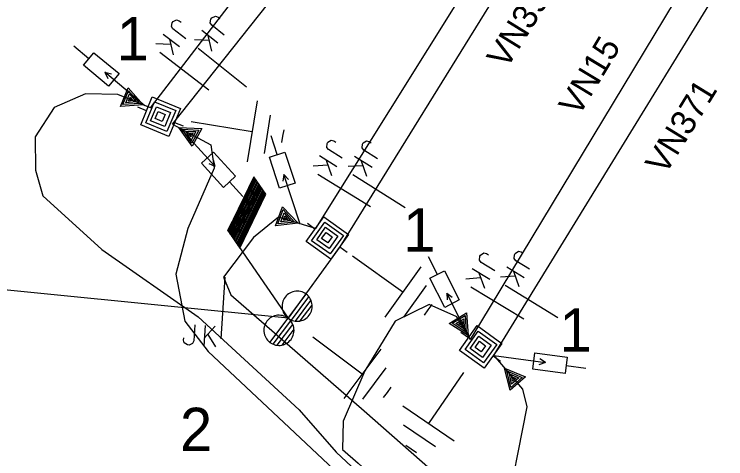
# Model space of a CAD drawing. Extents: x -540340 to -537226, y -1183949 to -1180375.
# Drawn here: x -537543.05 to -537514.32, y -1180671.08 to -1180653.13 of the extents above; entities that cross this region are included whole.
import ezdxf

# ---------------------------------------------------------------- set-up
doc = ezdxf.new("R2010")
doc.units = 0
for name, color, linetype in [('Vrstva 1', 7, 'Continuous'), ('Vrstva 11', 7, 'Continuous'), ('Vrstva 13', 7, 'Continuous'), ('Vrstva 14', 7, 'Continuous'), ('Vrstva 15', 7, 'Continuous'), ('Vrstva 16', 7, 'Continuous'), ('Vrstva 18', 7, 'Continuous'), ('Vrstva 19', 7, 'Continuous'), ('Vrstva 3', 7, 'Continuous'), ('Vrstva 5', 7, 'Continuous')]:
    doc.layers.add(name, color=color, linetype=linetype)

msp = doc.modelspace()

# ---------------------------------------------------------------- linework, layer by layer
at = {"layer": 'Vrstva 1'}
for points in [[(-537537.553, -1180656.912), (-537521.871, -1180636.493)], [(-537536.659, -1180657.565), (-537520.59, -1180637.312)], [(-537517.243, -1180639.978), (-537530.88, -1180661.777)], [(-537516.363, -1180640.64), (-537529.897, -1180662.526), (-537531.994, -1180665.405)], [(-537524.622, -1180666.267), (-537524.208, -1180665.581), (-537511.413, -1180644.384)], [(-537523.685, -1180666.914), (-537523.331, -1180666.336), (-537510.283, -1180645.074)], [(-537531.994, -1180665.406), (-537572.36, -1180661.377), (-537627.262, -1180751.899)]]:
    msp.add_lwpolyline(points, dxfattribs=at)
at = {"layer": 'Vrstva 11'}
for p, q in [((-537534.393, -1180661.91), (-537533.341, -1180659.735)), ((-537534.36, -1180661.957), (-537533.309, -1180659.783)), ((-537534.328, -1180662.005), (-537533.276, -1180659.83)), ((-537534.295, -1180662.052), (-537533.244, -1180659.878)), ((-537534.263, -1180662.1), (-537533.212, -1180659.926)), ((-537534.23, -1180662.147), (-537533.179, -1180659.974)), ((-537534.197, -1180662.195), (-537533.147, -1180660.021)), ((-537534.165, -1180662.242), (-537533.114, -1180660.069)), ((-537534.132, -1180662.29), (-537533.082, -1180660.117)), ((-537534.1, -1180662.337), (-537533.049, -1180660.165)), ((-537534.067, -1180662.385), (-537533.017, -1180660.212)), ((-537534.035, -1180662.432), (-537532.984, -1180660.26)), ((-537534.002, -1180662.48), (-537532.952, -1180660.308)), ((-537533.969, -1180662.527), (-537532.92, -1180660.356)), ((-537534.425, -1180661.862), (-537534.246, -1180661.492))]:
    msp.add_line(p, q, dxfattribs=at)
msp.add_lwpolyline([(-537533.371, -1180659.691), (-537534.426, -1180661.862), (-537533.939, -1180662.572), (-537532.89, -1180660.4)], close=True, dxfattribs=at)
msp.add_lwpolyline([(-537534.426, -1180661.862), (-537531.994, -1180665.405)], dxfattribs=at)
at = {"layer": 'Vrstva 13'}
for points in [[(-537537.945, -1180657.595), (-537537.476, -1180656.46)], [(-537537.735, -1180657.516), (-537537.384, -1180656.664)], [(-537537.476, -1180656.46), (-537536.34, -1180656.929)], [(-537537.384, -1180656.664), (-537536.532, -1180657.016)], [(-537537.71, -1180657.028), (-537538.056, -1180656.885)], [(-537537.544, -1180657.429), (-537537.309, -1180656.861)], [(-537537.309, -1180656.861), (-537536.741, -1180657.095)], [(-537536.532, -1180657.016), (-537536.883, -1180657.867)], [(-537536.34, -1180656.929), (-537536.809, -1180658.064)], [(-537537.361, -1180657.338), (-537537.244, -1180657.054)], [(-537537.244, -1180657.054), (-537536.96, -1180657.171)], [(-537536.96, -1180657.171), (-537537.077, -1180657.455)], [(-537536.741, -1180657.095), (-537536.976, -1180657.663)], [(-537536.883, -1180657.867), (-537537.735, -1180657.516)], [(-537536.976, -1180657.663), (-537537.544, -1180657.429)], [(-537537.077, -1180657.455), (-537537.361, -1180657.338)], [(-537536.575, -1180657.496), (-537536.229, -1180657.639)], [(-537536.809, -1180658.064), (-537537.945, -1180657.595)], [(-537531.264, -1180662.301), (-537530.548, -1180661.304)], [(-537530.548, -1180661.304), (-537529.55, -1180662.02)], [(-537530.906, -1180661.803), (-537531.21, -1180661.584)], [(-537531.042, -1180662.272), (-537530.504, -1180661.524)], [(-537530.504, -1180661.524), (-537529.756, -1180662.061)], [(-537530.835, -1180662.231), (-537530.477, -1180661.732)], [(-537530.477, -1180661.732), (-537529.978, -1180662.091)], [(-537530.637, -1180662.185), (-537530.458, -1180661.935)], [(-537530.387, -1180662.364), (-537530.637, -1180662.185)], [(-537530.458, -1180661.935), (-537530.208, -1180662.114)], [(-537530.208, -1180662.114), (-537530.387, -1180662.364)], [(-537529.978, -1180662.091), (-537530.336, -1180662.589)], [(-537529.756, -1180662.061), (-537530.293, -1180662.809)], [(-537529.55, -1180662.02), (-537530.266, -1180663.018)], [(-537530.266, -1180663.018), (-537531.264, -1180662.301)], [(-537530.293, -1180662.809), (-537531.042, -1180662.272)], [(-537530.336, -1180662.589), (-537530.835, -1180662.231)], [(-537529.908, -1180662.519), (-537529.604, -1180662.737)], [(-537532.727, -1180666.378), (-537531.261, -1180664.432)], [(-537531.261, -1180664.432), (-537531.314, -1180664.396), (-537531.37, -1180664.366), (-537531.429, -1180664.343), (-537531.49, -1180664.325), (-537531.553, -1180664.314), (-537531.617, -1180664.31), (-537531.68, -1180664.312), (-537531.743, -1180664.321), (-537531.805, -1180664.336), (-537531.865, -1180664.358), (-537531.923, -1180664.386), (-537531.977, -1180664.42), (-537532.027, -1180664.459), (-537532.073, -1180664.503), (-537532.114, -1180664.552), (-537532.15, -1180664.605), (-537532.18, -1180664.661), (-537532.203, -1180664.72), (-537532.221, -1180664.782), (-537532.232, -1180664.845), (-537532.236, -1180664.908), (-537532.234, -1180664.972), (-537532.225, -1180665.035), (-537532.21, -1180665.097), (-537532.188, -1180665.157), (-537532.16, -1180665.214), (-537532.126, -1180665.268), (-537532.087, -1180665.319), (-537532.043, -1180665.364), (-537531.994, -1180665.405), (-537531.941, -1180665.441), (-537531.885, -1180665.471), (-537531.826, -1180665.495), (-537531.764, -1180665.512), (-537531.701, -1180665.524), (-537531.638, -1180665.528), (-537531.574, -1180665.526), (-537531.511, -1180665.517), (-537531.449, -1180665.501), (-537531.389, -1180665.479), (-537531.332, -1180665.451), (-537531.278, -1180665.418), (-537531.227, -1180665.379), (-537531.182, -1180665.334), (-537531.141, -1180665.285), (-537531.105, -1180665.232), (-537531.075, -1180665.176), (-537531.051, -1180665.117), (-537531.034, -1180665.056), (-537531.022, -1180664.993), (-537531.018, -1180664.929), (-537531.02, -1180664.865), (-537531.029, -1180664.803), (-537531.045, -1180664.741), (-537531.066, -1180664.681), (-537531.094, -1180664.623), (-537531.128, -1180664.569), (-537531.167, -1180664.519), (-537531.212, -1180664.473), (-537531.26, -1180664.432)], [(-537531.86, -1180665.482), (-537531.15, -1180664.54)], [(-537531.697, -1180665.521), (-537531.067, -1180664.686)], [(-537531.499, -1180665.514), (-537531.02, -1180664.878)], [(-537531.994, -1180665.405), (-537532.047, -1180665.37), (-537532.103, -1180665.34), (-537532.162, -1180665.316), (-537532.224, -1180665.298), (-537532.287, -1180665.287), (-537532.35, -1180665.283), (-537532.414, -1180665.285), (-537532.477, -1180665.294), (-537532.539, -1180665.309), (-537532.599, -1180665.331), (-537532.656, -1180665.359), (-537532.71, -1180665.393), (-537532.761, -1180665.432), (-537532.806, -1180665.476), (-537532.847, -1180665.525), (-537532.883, -1180665.578), (-537532.913, -1180665.634), (-537532.937, -1180665.694), (-537532.954, -1180665.755), (-537532.966, -1180665.818), (-537532.97, -1180665.881), (-537532.968, -1180665.945), (-537532.959, -1180666.008), (-537532.943, -1180666.07), (-537532.921, -1180666.13), (-537532.893, -1180666.187), (-537532.86, -1180666.242), (-537532.821, -1180666.292), (-537532.776, -1180666.338), (-537532.727, -1180666.379), (-537532.674, -1180666.414), (-537532.618, -1180666.444), (-537532.559, -1180666.468), (-537532.498, -1180666.486), (-537532.435, -1180666.497), (-537532.371, -1180666.501), (-537532.307, -1180666.499), (-537532.245, -1180666.49), (-537532.183, -1180666.475), (-537532.123, -1180666.453), (-537532.065, -1180666.425), (-537532.011, -1180666.391), (-537531.961, -1180666.352), (-537531.915, -1180666.308), (-537531.874, -1180666.259), (-537531.838, -1180666.206), (-537531.808, -1180666.15), (-537531.785, -1180666.09), (-537531.767, -1180666.029), (-537531.756, -1180665.966), (-537531.752, -1180665.903), (-537531.754, -1180665.839), (-537531.763, -1180665.776), (-537531.778, -1180665.714), (-537531.8, -1180665.654), (-537531.828, -1180665.597), (-537531.862, -1180665.542), (-537531.901, -1180665.492), (-537531.945, -1180665.446), (-537531.994, -1180665.405)], [(-537532.593, -1180666.455), (-537531.883, -1180665.513)], [(-537532.43, -1180666.494), (-537531.801, -1180665.659)], [(-537532.232, -1180666.487), (-537531.753, -1180665.851)], [(-537525.07, -1180666.701), (-537524.353, -1180665.703)], [(-537524.847, -1180666.672), (-537524.31, -1180665.923)], [(-537524.353, -1180665.703), (-537523.355, -1180666.42)], [(-537524.31, -1180665.923), (-537523.562, -1180666.461)], [(-537524.711, -1180666.202), (-537525.015, -1180665.984)], [(-537524.641, -1180666.631), (-537524.283, -1180666.132)], [(-537524.283, -1180666.132), (-537523.784, -1180666.49)], [(-537524.442, -1180666.584), (-537524.263, -1180666.335)], [(-537524.263, -1180666.335), (-537524.014, -1180666.514)], [(-537523.784, -1180666.49), (-537524.142, -1180666.989)], [(-537523.562, -1180666.461), (-537524.099, -1180667.209)], [(-537523.355, -1180666.42), (-537524.072, -1180667.418)], [(-537524.072, -1180667.418), (-537525.07, -1180666.701)], [(-537524.099, -1180667.209), (-537524.847, -1180666.672)], [(-537524.142, -1180666.989), (-537524.641, -1180666.631)], [(-537524.193, -1180666.764), (-537524.442, -1180666.584)], [(-537524.014, -1180666.514), (-537524.193, -1180666.764)], [(-537523.713, -1180666.919), (-537523.41, -1180667.137)]]:
    msp.add_lwpolyline(points, dxfattribs=at)
at = {"layer": 'Vrstva 15'}
for points in [[(-537533.245, -1180656.623), (-537533.646, -1180659.091)], [(-537532.71, -1180657.198), (-537532.963, -1180658.753)], [(-537535.913, -1180657.456), (-537533.445, -1180657.857)], [(-537532.169, -1180657.795), (-537532.212, -1180658.057)], [(-537532.212, -1180658.057), (-537532.253, -1180658.31)], [(-537529.392, -1180662.882), (-537527.36, -1180664.339)], [(-537526.632, -1180663.323), (-537528.088, -1180665.355)], [(-537526.409, -1180664.076), (-537527.326, -1180665.356)], [(-537526.189, -1180664.851), (-537526.344, -1180665.067)], [(-537526.344, -1180665.067), (-537526.493, -1180665.275)], [(-537530.995, -1180666.149), (-537528.996, -1180667.65)], [(-537528.246, -1180666.651), (-537529.747, -1180668.65)], [(-537528.039, -1180667.409), (-537528.985, -1180668.668)], [(-537524.913, -1180667.592), (-537526.318, -1180669.659)], [(-537527.837, -1180668.188), (-537527.997, -1180668.401)], [(-537527.997, -1180668.401), (-537528.15, -1180668.606)], [(-537525.285, -1180670.362), (-537527.352, -1180668.956)], [(-537526.032, -1180670.603), (-537527.335, -1180669.718)], [(-537527.021, -1180670.693), (-537527.233, -1180670.549)], [(-537526.801, -1180670.842), (-537527.021, -1180670.693)]]:
    msp.add_lwpolyline(points, dxfattribs=at)
at = {"layer": 'Vrstva 16'}
for points in [[(-537540.04, -1180654.93), (-537540.652, -1180654.419)], [(-537540.255, -1180655.187), (-537539.832, -1180654.681)], [(-537539.832, -1180654.681), (-537538.82, -1180655.527)], [(-537539.243, -1180656.033), (-537540.255, -1180655.187)], [(-537537.775, -1180656.824), (-537539.391, -1180655.473)], [(-537539.391, -1180655.473), (-537539.126, -1180655.54)], [(-537539.391, -1180655.473), (-537539.278, -1180655.721)], [(-537538.82, -1180655.527), (-537539.243, -1180656.033)], [(-537536.356, -1180657.726), (-537534.931, -1180659.277)], [(-537532.429, -1180658.798), (-537532.679, -1180658.042)], [(-537535.49, -1180659.148), (-537535.004, -1180658.702)], [(-537535.004, -1180658.702), (-537534.112, -1180659.673)], [(-537532.747, -1180658.903), (-537532.12, -1180658.697)], [(-537532.12, -1180658.697), (-537531.707, -1180659.949)], [(-537534.931, -1180659.277), (-537535.011, -1180659.016)], [(-537532.333, -1180660.156), (-537532.747, -1180658.903)], [(-537534.598, -1180660.12), (-537535.49, -1180659.148)], [(-537534.931, -1180659.277), (-537535.185, -1180659.175)], [(-537532.164, -1180659.602), (-537532.199, -1180659.873)], [(-537531.503, -1180661.603), (-537532.164, -1180659.602)], [(-537532.164, -1180659.602), (-537531.974, -1180659.799)], [(-537534.112, -1180659.673), (-537534.598, -1180660.12)], [(-537534.358, -1180659.9), (-537533.819, -1180660.487)], [(-537531.707, -1180659.949), (-537532.333, -1180660.156)], [(-537525.963, -1180663.638), (-537526.325, -1180662.928)], [(-537526.262, -1180663.79), (-537525.674, -1180663.491)], [(-537525.674, -1180663.491), (-537525.076, -1180664.666)], [(-537525.663, -1180664.965), (-537526.262, -1180663.79)], [(-537524.624, -1180666.27), (-537525.579, -1180664.393)], [(-537525.579, -1180664.393), (-537525.362, -1180664.558)], [(-537525.579, -1180664.393), (-537525.573, -1180664.665)], [(-537525.076, -1180664.666), (-537525.663, -1180664.965)], [(-537523.686, -1180666.911), (-537521.6, -1180667.198)], [(-537522.112, -1180667.455), (-537522.022, -1180666.802)], [(-537522.022, -1180666.802), (-537520.715, -1180666.981)], [(-537521.6, -1180667.198), (-537521.827, -1180667.047)], [(-537520.715, -1180666.981), (-537520.805, -1180667.635)], [(-537521.6, -1180667.198), (-537521.859, -1180667.281)], [(-537520.761, -1180667.313), (-537519.971, -1180667.422)], [(-537520.805, -1180667.635), (-537522.112, -1180667.455)]]:
    msp.add_lwpolyline(points, dxfattribs=at)
at = {"layer": 'Vrstva 18'}
for points in [[(-537535.107, -1180653.321), (-537535.071, -1180653.275)], [(-537535.071, -1180653.275), (-537534.925, -1180653.202)], [(-537534.925, -1180653.202), (-537534.822, -1180653.246)], [(-537534.822, -1180653.246), (-537534.745, -1180653.307)], [(-537536.704, -1180653.624), (-537536.675, -1180653.473)], [(-537536.675, -1180653.473), (-537536.639, -1180653.426)], [(-537536.639, -1180653.426), (-537536.494, -1180653.351)], [(-537536.494, -1180653.351), (-537536.39, -1180653.394)], [(-537536.39, -1180653.394), (-537536.312, -1180653.454)], [(-537535.139, -1180653.472), (-537535.107, -1180653.321)], [(-537535.078, -1180653.57), (-537535.139, -1180653.472)], [(-537536.642, -1180653.722), (-537536.704, -1180653.624)], [(-537536.127, -1180654.117), (-537536.642, -1180653.722)], [(-537534.825, -1180654.298), (-537535.474, -1180653.784)], [(-537534.569, -1180653.973), (-537535.078, -1180653.57)], [(-537536.379, -1180654.445), (-537537.035, -1180653.941)], [(-537536.785, -1180654.133), (-537536.63, -1180654.773)], [(-537535.227, -1180653.98), (-537535.082, -1180654.622)], [(-537536.736, -1180654.344), (-537537.328, -1180654.324)], [(-537535.181, -1180654.192), (-537535.773, -1180654.162)], [(-537535.194, -1180656.199), (-537537.177, -1180654.676)], [(-537533.666, -1180656.068), (-537535.627, -1180654.517)], [(-537530.432, -1180658.503), (-537530.418, -1180658.35)], [(-537530.418, -1180658.35), (-537530.387, -1180658.299)], [(-537530.387, -1180658.299), (-537530.251, -1180658.209)], [(-537530.251, -1180658.209), (-537530.144, -1180658.241)], [(-537530.144, -1180658.241), (-537530.06, -1180658.293)], [(-537529.005, -1180658.527), (-537528.991, -1180658.373)], [(-537528.991, -1180658.373), (-537528.959, -1180658.323)], [(-537528.959, -1180658.323), (-537528.822, -1180658.235)], [(-537528.822, -1180658.235), (-537528.715, -1180658.267)], [(-537528.715, -1180658.267), (-537528.632, -1180658.32)], [(-537530.36, -1180658.593), (-537530.432, -1180658.503)], [(-537529.807, -1180658.934), (-537530.36, -1180658.593)], [(-537528.934, -1180658.618), (-537529.005, -1180658.527)], [(-537528.384, -1180658.963), (-537528.934, -1180658.618)], [(-537530.024, -1180659.286), (-537530.728, -1180658.852)], [(-537530.46, -1180659.017), (-537530.24, -1180659.638)], [(-537528.603, -1180659.313), (-537529.304, -1180658.874)], [(-537530.389, -1180659.223), (-537530.981, -1180659.263)], [(-537528.968, -1180659.247), (-537529.56, -1180659.282)], [(-537529.037, -1180659.041), (-537528.823, -1180659.663)], [(-537528.665, -1180660.908), (-537530.794, -1180659.598)], [(-537527.257, -1180660.946), (-537529.376, -1180659.619)], [(-537524.222, -1180662.853), (-537524.086, -1180662.762)], [(-537524.086, -1180662.762), (-537523.979, -1180662.793)], [(-537522.82, -1180662.787), (-537522.684, -1180662.697)], [(-537522.684, -1180662.697), (-537522.576, -1180662.729)], [(-537522.576, -1180662.729), (-537522.493, -1180662.781)], [(-537524.264, -1180663.057), (-537524.252, -1180662.904)], [(-537524.252, -1180662.904), (-537524.222, -1180662.853)], [(-537523.979, -1180662.793), (-537523.894, -1180662.844)], [(-537522.864, -1180662.991), (-537522.851, -1180662.838)], [(-537522.793, -1180663.081), (-537522.864, -1180662.991)], [(-537522.851, -1180662.838), (-537522.82, -1180662.787)], [(-537524.192, -1180663.147), (-537524.264, -1180663.057)], [(-537523.636, -1180663.483), (-537524.192, -1180663.147)], [(-537522.239, -1180663.421), (-537522.793, -1180663.081)], [(-537523.85, -1180663.837), (-537524.558, -1180663.409)], [(-537524.288, -1180663.572), (-537524.063, -1180664.19)], [(-537522.455, -1180663.774), (-537523.16, -1180663.341)], [(-537522.891, -1180663.506), (-537522.671, -1180664.126)], [(-537534.541, -1180663.744), (-537534.71, -1180666.238)], [(-537524.216, -1180663.776), (-537524.807, -1180663.822)], [(-537522.821, -1180663.711), (-537523.412, -1180663.752)], [(-537522.476, -1180665.447), (-537524.617, -1180664.155)], [(-537521.094, -1180665.394), (-537523.225, -1180664.087)], [(-537535.757, -1180665.674), (-537535.801, -1180666.322)], [(-537535.345, -1180665.702), (-537535.401, -1180666.527)], [(-537535.379, -1180666.213), (-537534.933, -1180665.73)], [(-537536.214, -1180666.294), (-537536.207, -1180666.196)], [(-537535.231, -1180666.055), (-537534.92, -1180666.559)], [(-537536.192, -1180666.404), (-537536.214, -1180666.294)], [(-537536.049, -1180666.483), (-537536.192, -1180666.404)], [(-537535.99, -1180666.487), (-537536.049, -1180666.483)], [(-537535.848, -1180666.427), (-537535.99, -1180666.487)], [(-537535.801, -1180666.322), (-537535.848, -1180666.427)]]:
    msp.add_lwpolyline(points, dxfattribs=at)
at = {"layer": 'Vrstva 19'}
for points in [[(-537538.765, -1180656.855), (-537538.453, -1180656.097)], [(-537538.453, -1180656.097), (-537537.851, -1180656.788)], [(-537538.431, -1180656.214), (-537537.986, -1180656.736), (-537538.663, -1180656.775), (-537538.431, -1180656.214)], [(-537538.397, -1180656.343), (-537538.134, -1180656.671), (-537538.545, -1180656.701), (-537538.397, -1180656.343)], [(-537538.373, -1180656.472), (-537538.271, -1180656.612), (-537538.44, -1180656.633), (-537538.373, -1180656.472)], [(-537538.38, -1180656.581), (-537538.365, -1180656.545), (-537538.347, -1180656.577), (-537538.38, -1180656.581)], [(-537537.851, -1180656.788), (-537538.765, -1180656.855)], [(-537535.871, -1180658.457), (-537536.398, -1180657.707)], [(-537536.398, -1180657.707), (-537535.482, -1180657.735)], [(-537535.88, -1180658.338), (-537536.269, -1180657.773), (-537535.592, -1180657.804), (-537535.88, -1180658.338)], [(-537535.901, -1180658.206), (-537536.128, -1180657.852), (-537535.717, -1180657.865), (-537535.901, -1180658.206)], [(-537535.482, -1180657.735), (-537535.871, -1180658.457)], [(-537535.911, -1180658.076), (-537535.999, -1180657.926), (-537535.828, -1180657.922), (-537535.911, -1180658.076)], [(-537535.893, -1180657.968), (-537535.912, -1180658.002), (-537535.927, -1180657.968), (-537535.893, -1180657.968)], [(-537532.5, -1180661.674), (-537532.22, -1180660.903)], [(-537532.193, -1180661.019), (-537531.727, -1180661.522), (-537532.401, -1180661.59), (-537532.193, -1180661.019)], [(-537532.22, -1180660.903), (-537531.59, -1180661.569)], [(-537532.154, -1180661.147), (-537531.878, -1180661.464), (-537532.287, -1180661.511), (-537532.154, -1180661.147)], [(-537532.125, -1180661.274), (-537532.016, -1180661.41), (-537532.184, -1180661.438), (-537532.125, -1180661.274)], [(-537531.59, -1180661.569), (-537532.5, -1180661.674)], [(-537532.127, -1180661.384), (-537532.113, -1180661.347), (-537532.094, -1180661.378), (-537532.127, -1180661.384)], [(-537525.49, -1180665.611), (-537524.786, -1180665.191)], [(-537524.839, -1180665.298), (-537524.795, -1180665.982), (-537525.36, -1180665.609), (-537524.839, -1180665.298)], [(-537524.786, -1180665.191), (-537524.718, -1180666.105)], [(-537524.718, -1180666.105), (-537525.49, -1180665.611)], [(-537524.889, -1180665.422), (-537524.875, -1180665.842), (-537525.222, -1180665.62), (-537524.889, -1180665.422)], [(-537524.947, -1180665.539), (-537524.949, -1180665.713), (-537525.097, -1180665.628), (-537524.947, -1180665.539)], [(-537525.017, -1180665.622), (-537524.984, -1180665.602), (-537524.989, -1180665.639), (-537525.017, -1180665.622)], [(-537523.026, -1180668.31), (-537523.25, -1180667.421)], [(-537523.25, -1180667.421), (-537522.405, -1180667.775)], [(-537522.993, -1180668.196), (-537523.153, -1180667.529), (-537522.533, -1180667.8), (-537522.993, -1180668.196)], [(-537522.964, -1180668.065), (-537523.05, -1180667.653), (-537522.671, -1180667.812), (-537522.964, -1180668.065)], [(-537522.405, -1180667.775), (-537523.026, -1180668.31)], [(-537522.928, -1180667.939), (-537522.956, -1180667.768), (-537522.795, -1180667.826), (-537522.928, -1180667.939)], [(-537522.872, -1180667.845), (-537522.902, -1180667.87), (-537522.904, -1180667.834), (-537522.872, -1180667.845)]]:
    msp.add_lwpolyline(points, dxfattribs=at)
at = {"layer": 'Vrstva 5'}
for points in [[(-537537.553, -1180656.912), (-537538.874, -1180656.367), (-537540.174, -1180656.342), (-537541.44, -1180656.898), (-537542.203, -1180658.073), (-537542.19, -1180659.42), (-537541.9, -1180660.457), (-537539.51, -1180662.628), (-537535.624, -1180665.351), (-537531.538, -1180669.106), (-537530.048, -1180670.81), (-537525.356, -1180675.203), (-537520.634, -1180679.488), (-537517.6, -1180682.56), (-537515.324, -1180684.078), (-537513.804, -1180684.574)], [(-537536.659, -1180657.565), (-537535.107, -1180658.402), (-537534.978, -1180659.35), (-537536.044, -1180661.779), (-537536.522, -1180663.622), (-537536.16, -1180665.522), (-537535.216, -1180666.749), (-537532.16, -1180669.611), (-537528.12, -1180673.417), (-537525.071, -1180676.392), (-537517.795, -1180682.792), (-537515.228, -1180684.492), (-537513.669, -1180684.903)], [(-537530.88, -1180661.777), (-537532.373, -1180661.319), (-537533.384, -1180662.138), (-537534.594, -1180663.747), (-537534.304, -1180664.462), (-537528.918, -1180669.148), (-537521.77, -1180675.432), (-537512.808, -1180681.594), (-537509.997, -1180683.987), (-537501.368, -1180690.23), (-537495.897, -1180693.015), (-537484.881, -1180695.744), (-537477.363, -1180695.954), (-537470.096, -1180697.063), (-537463.413, -1180697.101), (-537453.89, -1180696.053), (-537446.059, -1180695.542), (-537435.563, -1180695.142), (-537412.336, -1180694.313)], [(-537524.622, -1180666.267), (-537525.171, -1180665.347), (-537526.296, -1180664.853), (-537527.665, -1180665.525), (-537528.898, -1180667.527), (-537529.765, -1180669.565), (-537529.795, -1180670.7), (-537529.157, -1180671.263), (-537522.37, -1180677.438), (-537517.485, -1180682.211), (-537515.124, -1180683.606), (-537513.442, -1180684.149)], [(-537523.685, -1180666.914), (-537522.52, -1180668.268), (-537522.345, -1180668.988), (-537523.248, -1180673.562), (-537523.402, -1180675.142), (-537521.953, -1180677.098), (-537519.715, -1180679.454), (-537517.304, -1180681.781), (-537514.902, -1180683.27), (-537513.267, -1180683.855)]]:
    msp.add_lwpolyline(points, dxfattribs=at)

# ---------------------------------------------------------------- texts
at = {"layer": 'Vrstva 14'}
for s, p in [('1', (-537538.912, -1180654.992)), ('1', (-537527.343, -1180662.713)), ('1', (-537521.032, -1180666.753)), ('2', (-537536.36, -1180670.769))]:
    msp.add_text(s, height=1.75, dxfattribs=at).set_placement(p)
at = {"layer": 'Vrstva 3'}
for s, rotation, p in [('VN392', 58.268, (-537523.17, -1180655.377)), ('VN15', 58.884, (-537520.26, -1180657.297)), ('VN371', 58.464, (-537516.766, -1180659.658))]:
    msp.add_text(s, height=1, rotation=rotation, dxfattribs=at).set_placement(p)

doc.saveas('drawing.dxf')
